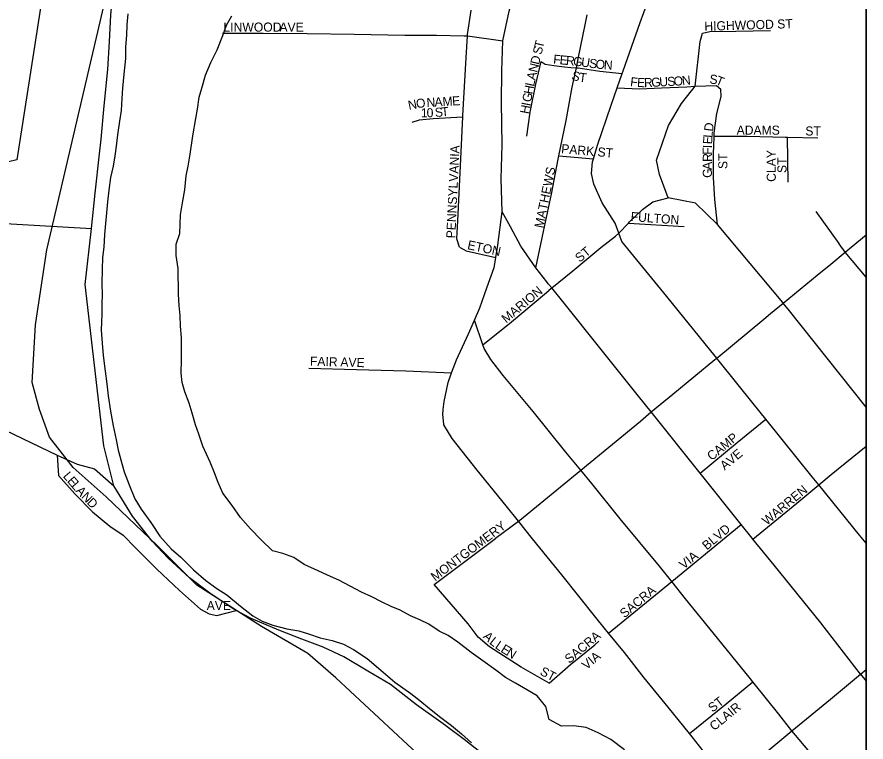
# Model space of a CAD drawing. Extents: x -84548 to 2262448, y -162180 to 525962.
# Drawn here: x 63175 to 67849, y 164137 to 168130 of the extents above; entities that cross this region are included whole.
import ezdxf

# ---------------------------------------------------------------- set-up
doc = ezdxf.new("R2010")
doc.units = 0
for name, color, linetype in [('GM_X_County', 7, 'Continuous'), ('GM_X_Interstate_Location', 7, 'Continuous'), ('GM_X_Major_Lake_Text', 7, 'Continuous'), ('GM_X_Township_Subdivision_Text', 7, 'Continuous'), ('GM_X_Unincorporated_Location', 7, 'Continuous'), ('GM_X_US_Location', 7, 'Continuous'), ('GM_X_US_Route', 7, 'Continuous')]:
    doc.layers.add(name, color=color, linetype=linetype)

msp = doc.modelspace()

# ---------------------------------------------------------------- linework, layer by layer
at = {"layer": 'GM_X_County'}
msp.add_line((67849.4, 170872.5), (67849.4, 134968.5), dxfattribs=at)
at = {"layer": 'GM_X_Interstate_Location'}
for points in [[(63785.9, 168147.1), (63780.9, 168086.8), (63777.8, 168030.6), (63772.8, 167966.3), (63773.8, 167902.1), (63763.1, 167815.7), (63756.3, 167737.3), (63753.2, 167681.1), (63748.3, 167614.8), (63739.2, 167556.5), (63728.4, 167480.1), (63721.3, 167417.8), (63714.1, 167365.5), (63705, 167309.2), (63690, 167246.7), (63681.1, 167176.4), (63674.1, 167112.1), (63656.9, 166931.2), (63654, 166863), (63646.9, 166804.7), (63643.9, 166738.5), (63643.1, 166662.2), (63644.1, 166600), (63642.9, 166549.9), (63641.7, 166495.7), (63639.2, 166405.4), (63644.3, 166333.2), (63649.4, 166265.1), (63660.8, 166179), (63669.9, 166108.9), (63676.9, 166042.9), (63690.3, 165958.8), (63705.5, 165878.8), (63720.8, 165800.8), (63731.7, 165744.8), (63746.6, 165690.9), (63765.6, 165625), (63792.8, 165553.2), (63824.1, 165475.5), (63859, 165419.9), (63912.2, 165346.5), (63961.4, 165271.1), (64024.6, 165201.9), (64077.4, 165154.6), (64146.6, 165085.5), (64215.6, 165026.4), (64276.4, 164983.3), (64331, 164948), (64406.1, 164885), (64473, 164832), (64525.5, 164802.7), (64583.9, 164781.6), (64660.3, 164760.8), (64726.6, 164749.8), (64780.9, 164732.6), (64845.3, 164711.6), (64909.7, 164696.6), (64972.1, 164675.5), (65028.6, 164646.3), (65103.5, 164597.4), (65166.4, 164544.2), (65255.7, 164467.4), (65342.8, 164404.6), (65393.5, 164365.3), (65446.2, 164322.1), (65509.1, 164272.9), (65567.9, 164227.7), (65622.6, 164182.5), (65677.5, 164133.2)], [(66519.1, 164094.6), (66444.1, 164151.6), (66375.4, 164188.6), (66308.9, 164217.6), (66238.7, 164226.5), (66172.6, 164225.4), (66106, 164260.5), (66086.8, 164332.4), (66039.8, 164391.8), (65985.3, 164423), (65920.6, 164462.1), (65864, 164493.3), (65811.3, 164532.6), (65740.4, 164583.6), (65675.6, 164630.7), (65602.6, 164687.7), (65550, 164722.9), (65499.5, 164748.2), (65442.9, 164785.4), (65392.4, 164810.7), (65342, 164831.9), (65285.5, 164863.1), (65235.1, 164884.4), (65182.6, 164909.6), (65128.1, 164936.8), (65071.7, 164962), (64946.5, 165028.2), (64884, 165055.2), (64833.5, 165080.5), (64756.9, 165115.4), (64700.2, 165152.6), (64639.8, 165175.7), (64581.5, 165190.8), (64520.4, 165250), (64461.4, 165311.2), (64406.3, 165374.5), (64359.3, 165440), (64308.1, 165507.4), (64283.1, 165567.1), (64262.3, 165619), (64239.3, 165678.8), (64197.9, 165766.4), (64176.8, 165832.3), (64158, 165884.1), (64139, 165948), (64124.1, 166003.9), (64099.1, 166065.7), (64084.2, 166117.6), (64079.4, 166167.7), (64080.3, 166241.9), (64081.2, 166310.2), (64080.3, 166364.3), (64075.3, 166426.4), (64074.4, 166486.6), (64067.5, 166540.6), (64064.6, 166602.8), (64062.3, 166745.2), (64051.2, 166817.2), (64052.2, 166879.4), (64071.3, 166937.9), (64074.5, 166988.1), (64075.7, 167040.3), (64086.7, 167106.7), (64099.6, 167177.1), (64106.3, 167255.5), (64117.5, 167307.8), (64128.5, 167374.2), (64142.9, 167474.7), (64159.4, 167571.3), (64168.6, 167621.6), (64177.6, 167687.9), (64192.8, 167738.3), (64213.8, 167808.9), (64242.7, 167879.6), (64277.6, 167948.3), (64308.4, 168027.1), (64329.6, 168085.6), (64358.8, 168136.2)]]:
    msp.add_lwpolyline(points, dxfattribs=at)
at = {"layer": 'GM_X_Major_Lake_Text'}
msp.add_line((67818.3, 164510.8), (67849.4, 164473), dxfattribs=at)
for points in [[(66091.5, 166671.9), (66031.4, 166747.7), (65948.4, 166868), (65891.6, 166973.8), (65846.9, 167057.6), (65841.5, 167237.8), (65846, 167426.1), (65842.2, 167658.4), (65844.8, 167832.7), (65849.7, 167998.1), (65884.3, 168161.5), (65944.7, 168376.3), (66012.8, 168631.2), (66081.1, 168862), (66131.8, 169030.7), (66176.8, 169163.2), (66230, 169275.8), (66377.7, 169540.7), (66566.6, 169855.9), (66662.7, 170015.6), (66716.4, 170104.7), (66999.5, 170583.9), (67099.2, 170752.6), (67165.1, 170872.5)], [(67222.2, 165260.1), (67161.7, 165334.2), (66936.2, 165618), (66667, 165954.6), (66597.4, 166041.8), (66369, 166326.4), (66195.1, 166545.4), (66119.3, 166637.6), (66103.4, 166656.9), (66100.2, 166660.9), (66091.5, 166671.9)], [(67818.3, 164510.8), (67599.9, 164793.5), (67343.2, 165112), (67226.8, 165254.4), (67222.2, 165260.1)], [(66423.3, 163356.5), (66469.5, 163394.1), (66497.9, 163417.2), (66666.9, 163554.7), (66840, 163696.2), (67046.8, 163866), (67095.4, 163907.4), (67243.6, 164033.7), (67441.2, 164199), (67653.3, 164373.3), (67818.3, 164510.8)]]:
    msp.add_lwpolyline(points, dxfattribs=at)
at = {"layer": 'GM_X_Township_Subdivision_Text'}
msp.add_lwpolyline([(67849.4, 159186.1), (67849.4, 170872.5), (66665.9, 170872.5), (66530.9, 170764.5), (66064.8, 170139.6), (66143.6, 169918.7), (66422.6, 170057.4), (66043.7, 169387.3), (65881.1, 169424.9), (65568, 169772.7), (65404.7, 169609.4), (64960, 169148.9), (64695, 168844), (64595.1, 168695.9), (63390, 168723.1), (63175.6, 167343.1), (63083.4, 167321.6), (63027, 167263.7), (62990.6, 167201.8), (61806.2, 167434.3), (60891.2, 167434.3), (60993.6, 168267), (60975.5, 168788.1), (57658.2, 168787.9)], dxfattribs=at)
at = {"layer": 'GM_X_Unincorporated_Location'}
msp.add_lwpolyline([(65797.8, 163683.4), (64931.5, 164490.9), (64776, 164625.2), (64522.4, 164772.8), (64164.9, 165001.2), (63947.4, 165219.4), (63665.8, 165488.3), (63484.8, 165649.3), (63354.2, 165815.8), (63299.3, 165969.2), (63259.3, 166117.3), (63278.1, 166434.9), (63339.6, 166846.8), (63719, 168473.8), (63928.7, 169095), (64101.1, 169498.7), (64298.3, 169920.8), (64528, 170252.9), (64755.1, 170520.2), (65072.7, 170872.5)], dxfattribs=at)
at = {"layer": 'GM_X_US_Location'}
msp.add_line((67818.3, 164510.8), (67849.4, 164536.2), dxfattribs=at)
for points in [[(63630.5, 167376.1), (63639.4, 167456.7), (63655.4, 167641.4), (63675.2, 167840.1), (63683.9, 167994.6), (63692.8, 168139), (63705.6, 168285.5), (63727, 168410.2), (63762.6, 168523.1), (63817.5, 168668.5), (63830.8, 168698.4), (63835.6, 168709.1)], [(66489.4, 166938.5), (66468.8, 166994.4), (66397.6, 167106), (66350.5, 167209.7), (66337.9, 167267.7), (66343.2, 167331.9), (66348.3, 167349.3), (66370.3, 167424.4), (66446.1, 167643.6), (66479.5, 167738.9), (66507.3, 167818.3), (66512.3, 167832.6), (66605.7, 168100), (66666, 168267), (66709.5, 168416.4)], [(65611.1, 166863), (65596.6, 166909), (65601.6, 167007.2), (65616.6, 167309.9), (65629.6, 167580.3), (65629.9, 167586.6), (65648.7, 167905.4), (65655, 168025.5), (65655.5, 168033.7), (65675, 168165.3), (65675.2, 168166.8)], [(66243, 167793), (66243, 167793.2), (66254.8, 167850), (66265, 167899.3), (66305.1, 168096.1), (66313.6, 168141.3), (66313.7, 168141.4)], [(64306.9, 168040.7), (64531, 168040.9), (64773.1, 168039.2), (65031.2, 168035.7), (65311.4, 168030.4), (65485.5, 168030.1), (65637.8, 168026.1), (65638.6, 168026.1)], [(65638.6, 168026.1), (65655, 168025.5), (65849.7, 167998.1)], [(66889.8, 167725), (66908.8, 167749.3), (66908.8, 167749.3), (66935.7, 167995.3), (66949.9, 168040.2)], [(66949.9, 168040.2), (66989.8, 168050.6), (67131.8, 168052), (67323.8, 168055.8)], [(65982.6, 167474), (66000.9, 167604.8), (66031.3, 167760), (66061.1, 167885.3)], [(66061.1, 167885.3), (66083.2, 167869.5), (66131.3, 167862), (66189.4, 167854.5), (66224.5, 167852.1), (66225.3, 167852)], [(66225.3, 167852), (66254.8, 167850), (66265.5, 167849.2), (66383.7, 167832.3), (66507.3, 167818.3)], [(66031.4, 166747.7), (66074.4, 166947.7), (66118.4, 167154.5), (66154.4, 167347.2), (66158.1, 167364.9), (66198.4, 167560), (66232.6, 167742.7), (66243, 167793)], [(66479.5, 167738.9), (66602.8, 167734.3), (66722.8, 167739.4), (66862.7, 167744.8), (66908.8, 167749.3), (67026.7, 167752.4), (67050.9, 167732.6)], [(66760.8, 167134.6), (66712.6, 167261.9), (66696.2, 167341.8), (66762.8, 167532.4), (66833.4, 167653), (66889.2, 167724.1), (66889.8, 167725)], [(67011.2, 167414.8), (67012.8, 167473.7), (67013.3, 167491.7), (67028.3, 167598.1), (67051.3, 167692.5), (67050.9, 167732.6)], [(61837.7, 167607.4), (61828.8, 167536.5), (61806.2, 167434.3), (61802.5, 167201.4), (61801.5, 167105.2), (61819.9, 167069.3), (61852.1, 167045.6), (62377.6, 167019.6), (62888.7, 167004.9), (63585.3, 166965.6)], [(65350.2, 167549.8), (65392, 167564.3), (65466, 167571), (65629.6, 167580.3)], [(67012.8, 167473.7), (67195.6, 167473.5), (67405.7, 167467.5), (67417.9, 167467.3), (67583.8, 167465.2)], [(67420.1, 167221.1), (67417.9, 167467.3)], [(63606.7, 167160.3), (63630.5, 167376.1)], [(67032.1, 166987), (67016.9, 167125.1), (67009.8, 167245.2), (67010.4, 167385.5), (67011.1, 167413.5), (67011.2, 167414.8)], [(66158.1, 167364.9), (66348.3, 167349.3)], [(65535.6, 164227.1), (65534.6, 164227.9), (65521.8, 164237.4), (65375.4, 164342.5), (65230.9, 164453.6), (65107.3, 164527.1), (64975.5, 164606.4), (64860.3, 164660.1), (64743.3, 164703.7), (64616.2, 164753), (64464.7, 164817.9), (64381.9, 164861.9), (64359.4, 164873.8), (64237.6, 164957.4), (64125.7, 165041.1), (64007.3, 165148.8), (63919.2, 165243.1), (63812.2, 165381), (63737.6, 165499.6), (63708.6, 165547.1), (63654, 165768.7), (63551, 166656.6), (63585.3, 166965.6), (63606.7, 167160.3)], [(66470.3, 166923.7), (66489.4, 166938.5), (66541.3, 166995), (66548, 167002.3), (66619.4, 167069.2), (66675, 167111.8), (66760.8, 167134.6)], [(67418.8, 166522.5), (67393.5, 166554.2), (67391.4, 166556.9), (67032.1, 166987), (66909.8, 167105), (66760.8, 167134.6)], [(65805.4, 166770.8), (65811.3, 166804.9), (65823.1, 166873.1), (65846.9, 167057.6)], [(67702.1, 166881.1), (67701.5, 166881.9), (67575.8, 167058.3)], [(66541.3, 166995), (66848.4, 166975.2)], [(66104.3, 166625.2), (66105.8, 166626.5), (66119.3, 166637.6), (66234.6, 166732.8), (66389.4, 166860.5), (66469.4, 166922.9), (66470.3, 166923.7)], [(67039.1, 166236.4), (67027.2, 166251.3), (66994.4, 166292.1), (66753.1, 166590.4), (66505.8, 166892.6), (66489.4, 166938.5)], [(67655.7, 166769.2), (67655.9, 166769.3), (67735.1, 166834.8), (67767.8, 166861.8), (67849.4, 166930.5)], [(65611.1, 166863), (65647.3, 166841.4), (65811.3, 166804.9)], [(67849.4, 166697), (67735.1, 166834.8), (67702.1, 166881.1)], [(65693.3, 166459.6), (65723.5, 166527.8), (65762.7, 166638.3), (65801.9, 166750.7), (65805.4, 166770.8)], [(67287, 166466.7), (67323.3, 166496.8), (67393.5, 166554.2), (67581.3, 166707.7), (67655.7, 166769.2)], [(65739.6, 166325), (65897.3, 166451), (66089.7, 166613.2), (66104.3, 166625.2)], [(67849.4, 165981.1), (67420.2, 166520.7), (67418.8, 166522.5)], [(65525.6, 165887.4), (65519.6, 165941.4), (65522.5, 165968.4), (65527.1, 166011.6), (65548.3, 166117.9), (65568, 166169.7), (65595.5, 166242.4), (65660.5, 166385.1), (65693.3, 166459.6)], [(67849.4, 163708.7), (67683, 163909.6), (67625, 163980.1), (67551.8, 164069.1), (67441.2, 164199), (67370.1, 164290.3), (67226.9, 164468), (67212.7, 164485.6), (67008.8, 164738.8), (66855.4, 164926.1), (66779.6, 165021), (66712, 165105.5), (66496.1, 165366.6), (66340.6, 165560), (66279.7, 165633.7), (66197.3, 165733.4), (66017.7, 165956.6), (65852.2, 166155.9), (65783.5, 166243.7), (65747.1, 166303.5), (65739.6, 166325), (65693.3, 166459.6)], [(65810.4, 165258.9), (65936.1, 165353.3), (65944.2, 165359.4), (66279.7, 165633.7), (66607, 165904.8), (66667, 165954.6), (66785.5, 166052.8), (67017.7, 166243.4), (67027.2, 166251.3), (67286.6, 166466.4), (67287, 166466.7)], [(62375.6, 166238.2), (62420.3, 166217.6), (62520.8, 166151.4), (62822.5, 165991.9), (63396.4, 165717.2), (63506.8, 165668.2), (63602.5, 165641.2), (63708.6, 165547.1)], [(67849.4, 165231.5), (67813.5, 165275.9), (67588.8, 165552.7), (67552, 165598.1), (67298, 165914.2), (67227.6, 166001.8), (67040.4, 166234.8), (67039.1, 166236.4)], [(64781.4, 166195.8), (65043.6, 166188.3), (65315.8, 166180.9), (65568, 166169.7)], [(66408.5, 164765.6), (66361.9, 164822.8), (66174.2, 165058), (66012.7, 165255.3), (65936.1, 165353.3), (65869.3, 165438.7), (65707.9, 165634), (65570.6, 165809.5), (65526, 165883.3), (65525.6, 165887.4)], [(66936.2, 165618), (67140.3, 165785.7), (67298, 165914.2)], [(67226.8, 165254.4), (67467.8, 165452.2), (67588.8, 165552.7), (67658.3, 165610.4), (67849.4, 165766.9)], [(63396.4, 165717.2), (63404.2, 165605.8), (63493.3, 165504.4), (63590.4, 165405.2), (63687.3, 165325.9), (63759.9, 165276.5), (63828.7, 165207.1), (63946, 165090), (64069.3, 164970.9), (64186.4, 164867.9), (64232.7, 164842.3), (64274.9, 164834.7), (64381.9, 164861.9)], [(66432.3, 164736.4), (66779.6, 165021), (67161.7, 165334.2)], [(65471.6, 165004.2), (65809.1, 165257.9), (65810.4, 165258.9)], [(66105.2, 164461.3), (65950.3, 164549.9), (65777.1, 164660.5), (65714.5, 164714), (65659.8, 164787.6), (65471.6, 165004.2)], [(67095.4, 163907.4), (67054.4, 163959.6), (66892.9, 164165), (66877.2, 164184.2), (66759.6, 164328.4), (66628.4, 164489.9), (66519.4, 164629.4), (66432.3, 164736.4), (66408.5, 164765.6)], [(66105.2, 164461.3), (66222.2, 164564.6), (66355.7, 164673.2), (66378.4, 164691.9)], [(66877.2, 164184.2), (67078.7, 164348.4), (67226.9, 164468)], [(65733.4, 164075.6), (65637.7, 164151.7), (65535.6, 164227.1)]]:
    msp.add_lwpolyline(points, dxfattribs=at)

# ---------------------------------------------------------------- texts
at = {"layer": 'GM_X_US_Route'}
for s, rotation, p in [('LINWOOD', 0, (64312.2, 168049.2)), ('AVE', 0, (64620.3, 168049.2)), ('HIGHWOOD ST', 1.7538, (66960.3, 168053.6)), ('T', 76.4607, (66070.6, 167953.9)), ('S', 76.4607, (66062.3, 167919.6)), ('D', 76.4541, (66048.9, 167864)), ('F', 354.4852, (66125.8, 167873.2)), ('E', 354.4852, (66160.9, 167869.8)), ('R', 354.4779, (66195.9, 167866.4)), ('G', 353.8348, (66235.1, 167862.6)), ('U', 352.097, (66278.5, 167858)), ('S', 352.065, (66322.1, 167851.9)), ('O', 353.5312, (66358.3, 167846.9)), ('N', 356.3673, (66404.7, 167841.7)), ('N', 76.4753, (66038.7, 167821.2)), ('A', 76.7695, (66028.6, 167778.4)), ('S', 343.1333, (66224.8, 167786.3)), ('T', 352.3271, (66267.1, 167774.3)), ('F', 352.7971, (66549.1, 167749.9)), ('E', 356.7526, (66587.8, 167745.1)), ('R', 2.0302, (66628, 167743.1)), ('G', 3.0547, (66668.5, 167744.5)), ('U', 3.0501, (66712.5, 167746.9)), ('S', 3.048, (66756.4, 167749.2)), ('O', 3.0392, (66791.6, 167751.1)), ('N', 6.0561, (66838.4, 167753.7)), ('S', 355.4179, (66986.4, 167763.3)), ('T', 338.2671, (67017.6, 167761.4)), ('H', 79.4201, (66013.4, 167701.4)), ('L', 78.1142, (66021.4, 167744.3)), ('G', 79.4201, (66005.3, 167658.1)), ('N', 11.4535, (65333.5, 167618)), ('O', 8.5891, (65376, 167626.6)), ('N', 3.3023, (65431.5, 167633.9)), ('A', 3.3023, (65475.4, 167636.4)), ('M', 3.298, (65519.3, 167638.9)), ('E', 3.3109, (65572.1, 167642)), ('I', 79.4058, (66001.3, 167636.5)), ('1', 0.3591, (65399.1, 167576.6)), ('0', 1.9514, (65431.5, 167576.9)), ('S', 4.5439, (65477.9, 167578.9)), ('T', 5.6078, (65514, 167581.7)), ('H', 79.4273, (65993.2, 167593.2)), ('D', 82.4819, (67006.4, 167497.3)), ('ADAMS', 0, (67137, 167481.6)), ('ST', 0, (67515.4, 167477.2)), ('E', 86.8565, (67001.7, 167428.1)), ('L', 85.2409, (67003.6, 167462.9)), ('PENNSYLVANIA', 87.3509, (65588.3, 166910)), ('PARK ST', 354.9858, (66169.8, 167380.4)), ('I', 88.251, (67001, 167406.5)), ('F', 89.8634, (67000.9, 167371.6)), ('R', 89.8786, (67000.8, 167332)), ('ST', 90, (67086.1, 167292.5)), ('CLAY', 90, (67352.7, 167222)), ('A', 89.8803, (67000.8, 167288)), ('ST', 90, (67411.7, 167270.4)), ('MATHEWS', 78.5305, (66072.4, 166964.2)), ('G', 89.8689, (67000.7, 167244)), ('FULTON', 355.8407, (66552.5, 167006.4)), ('ETON', 347.8012, (65651.7, 166852.2)), ('ST', 39.8038, (66273.4, 166775.6)), ('MARION', 39.9363, (65868.6, 166441.2)), ('FAIR', 358.2112, (64787.7, 166210)), ('AVE', 358.0261, (64955, 166205.6)), ('CAMP', 38.8857, (66999.5, 165684.5)), ('AVE', 39.5598, (67071.4, 165631.8)), ('L', 310.5806, (63425.8, 165599.7)), ('E', 310.5806, (63448.7, 165573)), ('L', 310.5806, (63471.6, 165546.2)), ('WARREN', 39.5612, (67303.1, 165328)), ('A', 312.6585, (63495.8, 165518)), ('N', 313.6456, (63526.2, 165485)), ('D', 313.7252, (63556.6, 165453.1)), ('MONTGOMERY', 36.9833, (65477.4, 165020.3)), ('BLVD', 39.6115, (66973, 165191.6)), ('VIA', 38.6625, (66845.6, 165086.1)), ('SACRA', 39.6455, (66519.8, 164817.6)), ('AVE', 0, (64219.8, 164863.6)), ('A', 317.1914, (65737.3, 164713.9)), ('L', 321.5841, (65772.7, 164681.3)), ('SACRA', 39.8062, (66216.2, 164566.8)), ('L', 325.9768, (65803.7, 164656.9)), ('E', 328.1731, (65834.6, 164636.1)), ('N', 328.1731, (65864.5, 164617.5)), ('VIA', 40.1007, (66310.8, 164532.3)), ('ST', 331.9283, (66050, 164510.6)), ('ST', 37.5682, (67004.1, 164298.6)), ('CLAIR', 39.2948, (67013.6, 164196.9))]:
    msp.add_text(s, height=50, rotation=rotation, dxfattribs=at).set_placement(p)

doc.saveas('drawing.dxf')
